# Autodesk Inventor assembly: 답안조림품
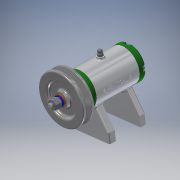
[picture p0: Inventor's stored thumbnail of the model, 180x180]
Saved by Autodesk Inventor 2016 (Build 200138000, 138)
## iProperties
Created: 2018-05
Part Number: 답안조림품
Material: 일반
Document SubType Name: Assembly
Designer: USER
Author: USER
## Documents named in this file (16)
- C:\Users\USER\Desktop\480507V1027\답안조림품.iam
- C:\Users\USER\Desktop\480507V1027\본체.ipt
- C:\Users\USER\Desktop\480507V1027\축.ipt
- C:\Users\USER\Desktop\480507V1027\베어링 6002.ipt
- C:\Users\USER\Desktop\480507V1027\뒤커버.ipt
- C:\Users\USER\Desktop\480507V1027\앞커버.ipt
- C:\Users\USER\Desktop\480507V1027\V벨트풀리.ipt
- C:\Users\USER\Desktop\480507V1027\키 3x3x12.ipt
- C:\Users\USER\Desktop\480507V1027\볼트 M4x12.ipt
- C:\Users\USER\Desktop\480507V1027\니플 M6x0.75.ipt
- C:\Users\USER\Desktop\480507V1027\볼트 M6x8.ipt
- C:\Users\USER\Desktop\480507V1027\와셔 6x11.5.ipt
- C:\Users\USER\Desktop\480507V1027\와셔 8x17.ipt
- C:\Users\USER\Desktop\480507V1027\오일 실 15 25 7.ipt
- C:\Users\USER\Desktop\480507V1027\스프링와셔 8.ipt
- C:\Users\USER\Desktop\480507V1027\너트 M8.ipt
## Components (1 placed, 1 different names)
1. V벨트풀리:1
